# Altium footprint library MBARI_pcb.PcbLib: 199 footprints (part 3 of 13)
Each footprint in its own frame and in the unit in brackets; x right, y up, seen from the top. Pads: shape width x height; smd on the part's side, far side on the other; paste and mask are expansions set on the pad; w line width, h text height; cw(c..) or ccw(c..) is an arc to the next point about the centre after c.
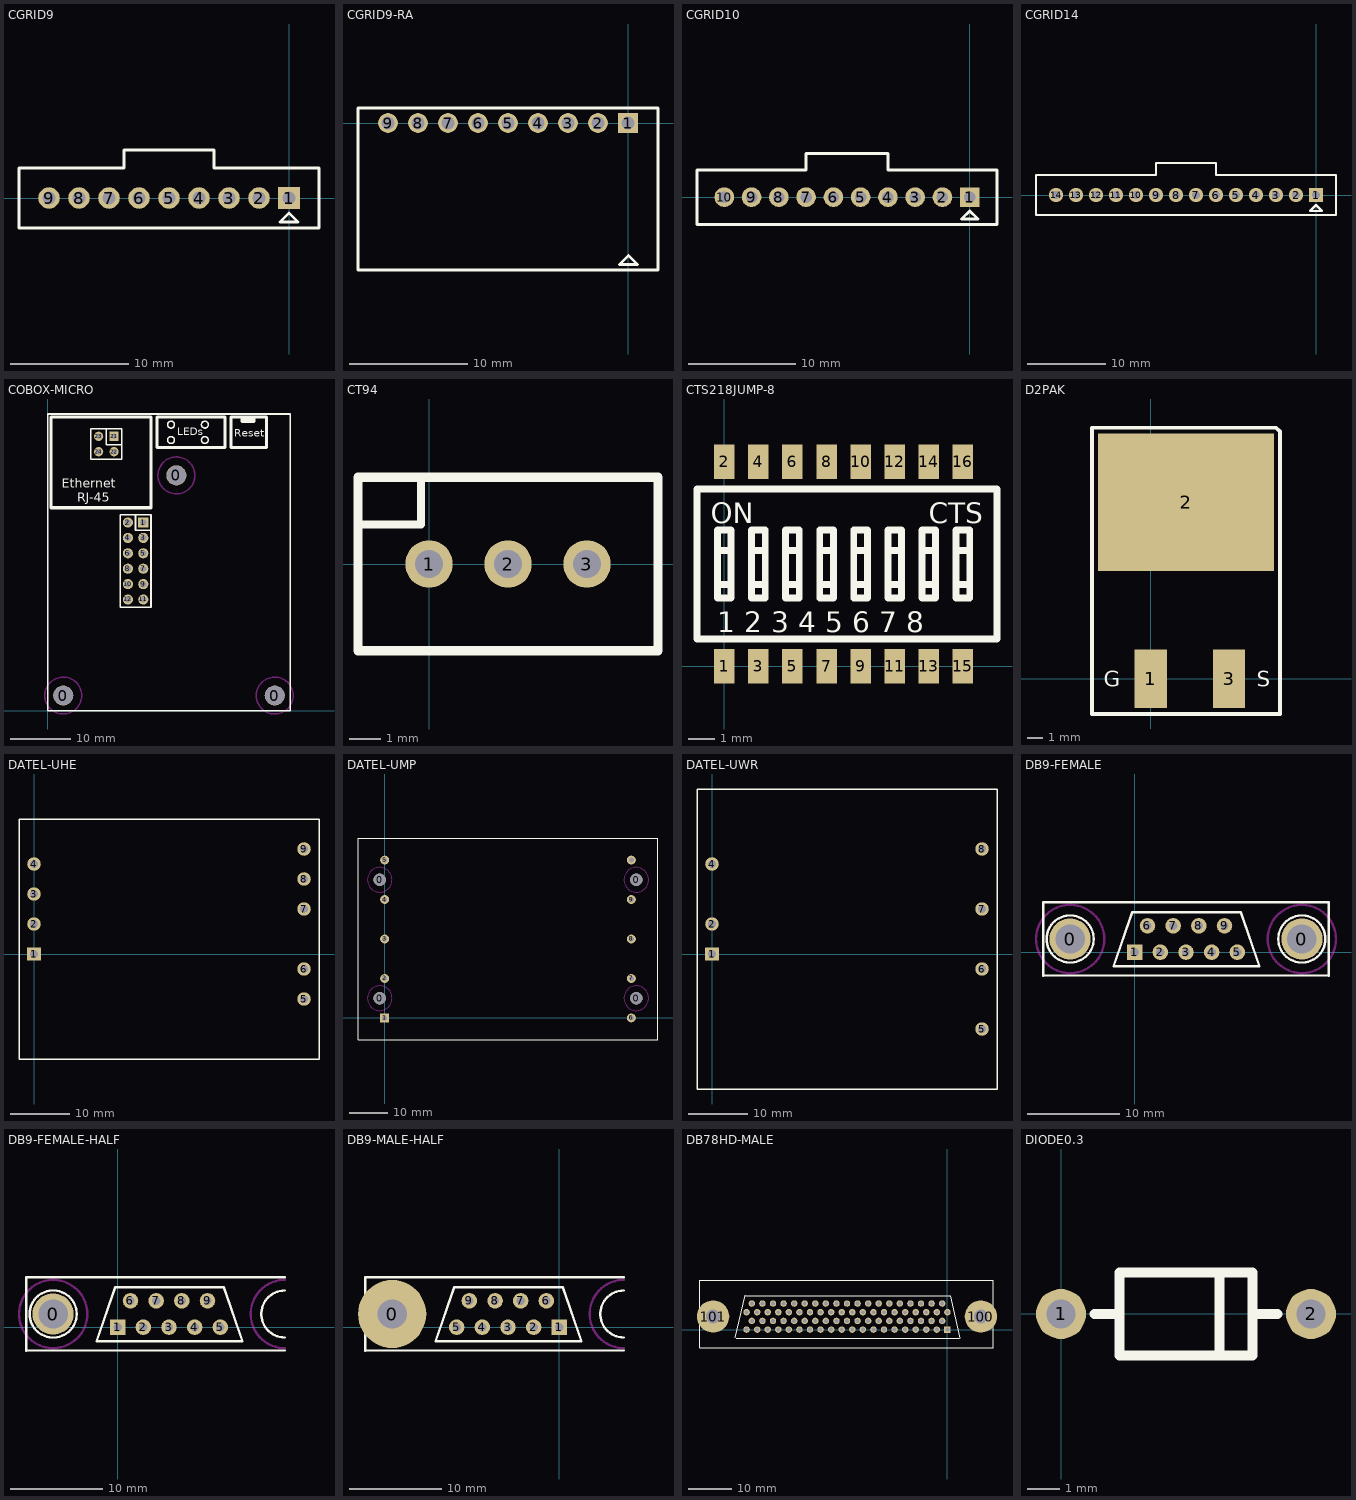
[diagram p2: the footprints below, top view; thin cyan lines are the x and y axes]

## CGRID9 [mil]
pads (9):
  rect 72x72 hole 42: 1(0,0)
  round 72 hole 42: 2(-100,0) 3(-200,0) 4(-300,0) 5(-400,0) 6(-500,0) 7(-600,0) 8(-700,0) 9(-800,0)
TopOverlay:
  lines w10: -900,-100 100,-100 100,100 -250,100 -250,160 -550,160 -550,100 -900,100 -900,-100 ; -30,-80 0,-50 30,-80 -30,-80

## CGRID9-RA [mil]
pads (9):
  rect 66x66 hole 42: 1(0,0)
  round 66 hole 42: 2(-100,0) 3(-200,0) 4(-300,0) 5(-400,0) 6(-500,0) 7(-600,0) 8(-700,0) 9(-800,0)
TopOverlay:
  lines w10: -900,-490 100,-490 100,50 -900,50 -900,-490 ; -28.29,-471.71 1.71,-441.71 31.71,-471.71 -28.29,-471.71

## CGRID10 [mil] "10 pin Molex CGRID-SL straight"
pads (10):
  rect 72x72 hole 42: 1(0,0)
  round 72 hole 42: 2(-100,0) 3(-200,0) 4(-300,0) 5(-400,0) 6(-500,0) 7(-600,0) 8(-700,0) 9(-800,0) 10(-900,0)
TopOverlay:
  lines w10: -1000,-100 100,-100 100,100 -300,100 -300,160 -600,160 -600,100 -1000,100 -1000,-100 ; -30,-80 0,-50 30,-80 -30,-80

## CGRID14 [mil]
pads (14):
  rect 72x72 hole 42: 1(0,0)
  round 72 hole 42: 2(-100,0) 3(-200,0) 4(-300,0) 5(-400,0) 6(-500,0) 7(-600,0) 8(-700,0) 9(-800,0) 10(-900,0) 11(-1000,0) 12(-1100,0) 13(-1200,0) 14(-1300,0)
TopOverlay:
  lines w10: -1400,-100 100,-100 100,100 -500,100 -500,160 -800,160 -800,100 -1400,100 -1400,-100 ; -30,-80 0,-50 30,-80 -30,-80

## COBOX-MICRO [mil]
pads (19):
  round 130 hole 125: 0(100,100) 0(835,1530) 0(1474,100)
  rect 66x66 hole 42: 1(620,1224)
  round 66 hole 42: 2(520,1224) 3(620,1124) 4(520,1124) 5(620,1024) 6(520,1024) 7(620,924) 8(520,924) 9(620,824) 10(520,824) 11(620,724) 12(520,724)
  rect 60x60 hole 35: 21(430,1784)
  round 60 hole 35: 22(430,1684) 23(330,1784) 24(330,1684)
TopOverlay:
  circle w10: c800,1860 r22.36
  circle w10: c800,1760 r22.36
  circle w10: c1020,1860 r22.36
  circle w10: c1020,1760 r22.36
  lines w10: 380,1834 380,1730 480,1730 ; 0,0 0,1929 1574,1929 1574,0 0,0 ; 280,1634 480,1634 480,1834 280,1834 280,1634
  lines w12: 570,1274 570,1174 670,1174 ; 470,674 470,1274 670,1274 670,674 470,674
  lines w20: 1260,1910 1260,1880 1340,1880 1340,1910 ; 1270,1890 1340,1890 ; 1280,1900 1330,1900 ; 20,1320 660,1320 670,1320 670,1910 20,1910 20,1320 ; 710,1710 710,1910 1150,1910 1150,1710 710,1710 ; 1190,1710 1190,1910 1420,1910 1420,1710 1190,1710
  text "RJ-45" at 190,1360 h60
  text "Reset" at 1210,1780 h50
  text "LEDs" at 840,1790 h50
  text "Ethernet" at 90,1450 h60
KeepOutLayer:
  circle w10: c100,100 r120
  circle w10: c1474,100 r120
  circle w10: c835,1530 r120

## CT94 [mil]
pads (3):
  round 60 hole 35: 1(0,0) 2(100,0) 3(200,0)
TopOverlay:
  lines w10: -90,50 -10,50 -10,110
  lines w12: -90,-110 290,-110 290,110 -90,110 -90,-10 -90,-110

## CTS218JUMP-8 [mil]
pads (16):
  rect 30x50 smd: 1(0,0) 2(0,300) 3(50,0) 4(50,300) 5(100,0) 6(100,300) 7(150,0) 8(150,300) 9(200,0) 10(200,300) 11(250,0) 12(250,300) 13(300,0) 14(300,300) 15(350,0) 16(350,300)
TopOverlay:
  lines w10: -10,120 10,120 ; -10,170 10,170 ; 40,120 60,120 ; 40,170 60,170 ; 90,120 110,120 ; 90,170 110,170 ; 140,120 160,120 ; 140,170 160,170 ; 190,120 210,120 ; 190,170 210,170 ; 240,120 260,120 ; 240,170 260,170 ; 290,120 310,120 ; 290,170 310,170 ; 340,120 360,120 ; 340,170 360,170 ; -40,40 -40,260 400,260 400,40 -40,40 ; -10,100 -10,200 10,200 10,100 -10,100 ; 40,100 40,200 60,200 60,100 40,100 ; 90,100 90,200 110,200 110,100 90,100 ; 140,100 140,200 160,200 160,100 140,100 ; 190,100 190,200 210,200 210,100 190,100 ; 240,100 240,200 260,200 260,100 240,100 ; 290,100 290,200 310,200 310,100 290,100 ; 340,100 360,100 360,200 340,200 340,100
  text "1 2 3 4 5 6 7 8" at -10,50 h30
  text "CTS" at 300,210 h30
  text "ON" at -20,210 h30

## D2PAK [mil] "IRF D2Pak SMD-220"
height 175
pads (3):
  rect 82x150 smd: 1(0,0) 3(200,0)
  rect 450x350 smd: 2(90,450)
TopOverlay:
  lines w10: -150,-90 -150,640 320,640 330,630 330,-90 -150,-90
  text "S" at 270,-20 h40
  text "G" at -120,-20 h40

## DATEL-UHE [mil] "Datel UHE 1.6x2.0 DC/DC Converter"
height 420
pads (9):
  rect 90x90 hole 52: 1(0,0)
  round 90 hole 52: 2(0,200) 3(0,400) 4(0,600) 5(1800,-300) 6(1800,-100) 7(1800,300) 8(1800,500) 9(1800,700)
TopOverlay:
  lines w10: -100,-700 1900,-700 1900,900 -100,900 -100,-700
BottomOverlay:
  text "5" at 1720,-320 h40
  text "9" at 1720,690 h40
  text "4" at 100,590 h40

## DATEL-UMP [mil]
pads (14):
  round 125 hole 125: 0(-50,200) 0(-50,1400) 0(2550,200) 0(2550,1400)
  rect 90x90 hole 52: 1(0,0)
  round 90 hole 52: 2(0,400) 3(0,800) 4(0,1200) 5(0,1600) 6(2500,0) 7(2500,400) 8(2500,800) 9(2500,1200) 10(2500,1600)
TopOverlay:
  lines w10: -270,-220 2770,-220 2770,1820 -270,1820 -270,-220
KeepOutLayer:
  circle w10: c-50,1400 r125
  circle w10: c-50,200 r125
  circle w10: c2550,200 r125
  circle w10: c2550,1400 r125

## DATEL-UWR [mil]
pads (7):
  rect 90x90 hole 52: 1(0,0)
  round 90 hole 52: 2(0,200) 4(0,600) 5(1800,-500) 6(1800,-100) 7(1800,300) 8(1800,700)
TopOverlay:
  lines w10: -100,-900 1900,-900 1900,1100 -100,1100 -100,-900

## DB9-FEMALE [mil]
pads (11):
  round 175 hole 125: 0(-274,56) 0(710,56)
  rect 66x66 hole 35: 1(0,0)
  round 66 hole 35: 2(109,0) 3(218,0) 4(327,0) 5(436,0) 6(54.5,112) 7(163.5,112) 8(272.5,112) 9(381.5,112)
TopOverlay:
  circle w10: c-274,56 r100
  circle w10: c710,56 r100
  lines w8: -388.5,-99.5 824.5,-99.5
  lines w10: -388.5,-99.5 -388.5,211.5 824.5,211.5 824.5,-99.5 ; -90,-60 -10,170 450,170 530,-60 -90,-60
KeepOutLayer:
  circle w10: c-274,56 r145
  circle w10: c710,56 r145

## DB9-FEMALE-HALF [mil]
pads (10):
  round 175 hole 125: 0(-274,56)
  rect 66x66 hole 35: 1(0,0)
  round 66 hole 35: 2(109,0) 3(218,0) 4(327,0) 5(436,0) 6(54.5,112) 7(163.5,112) 8(272.5,112) 9(381.5,112)
TopOverlay:
  circle w10: c-274,56 r100
  lines w8: -388.5,-99.5 710,-99.5
  lines w10: -388.5,-99.5 -388.5,211.5 710,211.5 ; 710,-44 cw(c710,56) 710,156 ; -90,-60 530,-60 450,170 -10,170 -90,-60
KeepOutLayer:
  circle w10: c-274,56 r145
  lines w10: 710,-89 cw(c710,56) 710,201

## DB9-MALE-HALF [mil]
pads (10):
  round 290 hole 125: 0(-710,56)
  rect 66x66 hole 35: 1(0,0)
  round 66 hole 35: 2(-109,0) 3(-218,0) 4(-327,0) 5(-436,0) 6(-55,112) 7(-164,112) 8(-273,112) 9(-382,112)
TopOverlay:
  circle w10: c-710,56 r100
  lines w8: -824.5,-99.5 274,-99.5
  lines w10: -824.5,-99.5 -824.5,211.5 274,211.5 ; 274,-44 cw(c274,56) 274,156 ; -526,-60 94,-60 14,170 -446,170 -526,-60
KeepOutLayer:
  lines w10: 274,-89 cw(c274,56) 274,201

## DB78HD-MALE [mil]
pads (80):
  rect 58x58 hole 35: 1(0,0)
  round 58 hole 35: 2(-95,0) 3(-190,0) 4(-285,0) 5(-380,0) 6(-475,0) 7(-570,0) 8(-665,0) 9(-760,0) 10(-855,0) 11(-950,0) 12(-1045,0) 13(-1140,0) 14(-1235,0) 15(-1330,0) 16(-1425,0) 17(-1520,0) 18(-1615,0) 19(-1710,0) 20(-1805,0) 21(-47.5,78) 22(-142.5,78) 23(-237.5,78) 24(-332.5,78) 25(-427.5,78) 26(-522.5,78) 27(-617.5,78) 28(-712.5,78) 29(-807.5,78) 30(-902.5,78) 31(-997.5,78) 32(-1092.5,78) 33(-1187.5,78) 34(-1282.5,78) 35(-1377.5,78) 36(-1472.5,78) 37(-1567.5,78) 38(-1662.5,78) 39(-1757.5,78) 40(0,156) 41(-95,156) 42(-190,156) 43(-285,156) 44(-380,156) 45(-475,156) 46(-570,156) 47(-665,156) 48(-760,156) 49(-855,156) 50(-950,156) 51(-1045,156) 52(-1140,156) 53(-1235,156) 54(-1330,156) 55(-1425,156) 56(-1520,156) 57(-1615,156) 58(-1710,156) 59(-1805,156) 60(-47.5,234) 61(-142.5,234) 62(-237.5,234) 63(-332.5,234) 64(-427.5,234) 65(-522.5,234) 66(-617.5,234) 67(-712.5,234) 68(-807.5,234) 69(-902.5,234) 70(-997.5,234) 71(-1092.5,234) 72(-1187.5,234) 73(-1282.5,234) 74(-1377.5,234) 75(-1472.5,234) 76(-1567.5,234) 77(-1662.5,234) 78(-1757.5,234)
  round 290 hole 125: 100(300.5,117) 101(-2105.5,117)
TopOverlay:
  lines w10: -1905,-73 -1815,307 ; -1897,-77.5 108,-76 ; -1815,305 27,305 110,-76 ; -2228,-163 410,-163 410,443 -2228,443 -2228,-163

## DIODE0.3 [mil]
pads (2):
  round 60 hole 35: 1(0,0) 2(300,0)
TopOverlay:
  lines w12: 40,0 70,0 ; 190,-50 190,50 ; 230,0 260,0 ; 70,-50 70,50 230,50 230,-50 70,-50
